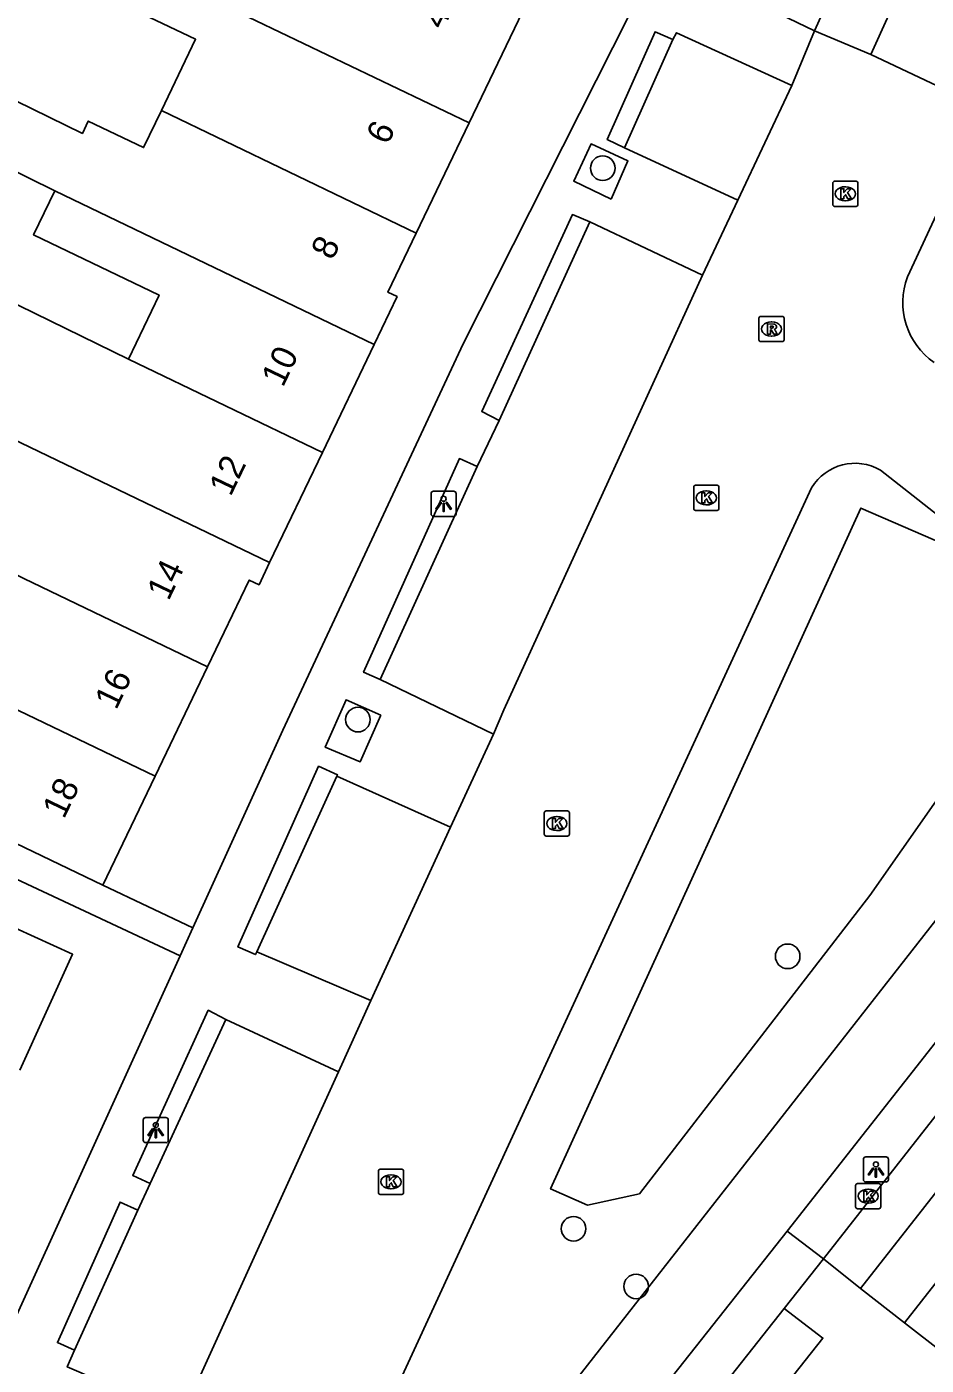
# Model space of a CAD drawing. Extents: x 161355 to 162026, y 386504 to 387459.
# Drawn here: x 161710.6 to 161746.4, y 387097.6 to 387150.7 of the extents above; entities that cross this region are included whole.
import ezdxf

# ---------------------------------------------------------------- set-up
doc = ezdxf.new("R2010")
doc.units = 0
for name, color, linetype in [('IMGEO_Boom', 7, 'Continuous'), ('IMGEO_Groenvoorziening', 7, 'Continuous'), ('IMGEO_Kolk', 7, 'Continuous'), ('IMGEO_Lichtpunt', 7, 'Continuous'), ('IMGEO_Pand', 7, 'Continuous'), ('IMGEO_Pand_nummerreeks', 7, 'Continuous'), ('IMGEO_Parkeervlak_open', 7, 'Continuous'), ('IMGEO_Rijbaan_lokaal_gesloten', 7, 'Continuous'), ('IMGEO_Rijbaan_lokaal_open', 7, 'Continuous'), ('IMGEO_Rioolput', 7, 'Continuous'), ('IMGEO_Voetpad_open', 7, 'Continuous')]:
    doc.layers.add(name, color=color, linetype=linetype)

msp = doc.modelspace()

# ---------------------------------------------------------------- linework, layer by layer
at = {"layer": 'IMGEO_Boom'}
for centre in [(161733.509, 387145.125), (161723.775, 387123.211), (161740.861, 387113.805), (161732.348, 387102.979), (161734.836, 387100.687)]:
    msp.add_circle(centre, 0.489, dxfattribs=at)
at = {"layer": 'IMGEO_Groenvoorziening'}
for points in [[(161732.906, 387103.919), (161734.966, 387104.367), (161744.13, 387116.217), (161750.489, 387125.292), (161750.19, 387127.083), (161747.533, 387129.979), (161743.772, 387131.62), (161731.438, 387104.561), (161732.906, 387103.919)], [(161754.575, 387125.244), (161721.108, 387082.503), (161720.967, 387082.324), (161720.779, 387082.098), (161720.566, 387081.91), (161720.265, 387081.76), (161719.863, 387081.722), (161719.475, 387081.835), (161719.261, 387082.023), (161719.123, 387082.287), (161718.998, 387082.525), (161718.9, 387082.743)]]:
    msp.add_lwpolyline(points, dxfattribs=at)
at = {"layer": 'IMGEO_Kolk'}
for p, q in [((161742.653, 387143.68), (161742.653, 387144.532)), ((161742.728, 387144.606), (161743.58, 387144.606)), ((161743.141, 387144.386), (161743.166, 387144.386)), ((161743.654, 387144.532), (161743.654, 387143.68)), ((161743.58, 387143.606), (161742.728, 387143.606)), ((161743.164, 387143.826), (161743.139, 387143.826)), ((161737.125, 387131.597), (161737.125, 387132.449)), ((161737.2, 387132.523), (161738.052, 387132.523)), ((161738.126, 387132.449), (161738.126, 387131.597)), ((161737.613, 387132.303), (161737.638, 387132.303)), ((161738.052, 387131.523), (161737.2, 387131.523)), ((161737.636, 387131.743), (161737.611, 387131.743)), ((161731.185, 387118.656), (161731.185, 387119.508)), ((161731.26, 387119.582), (161732.112, 387119.582)), ((161731.673, 387119.362), (161731.698, 387119.362)), ((161732.186, 387119.508), (161732.186, 387118.656)), ((161732.112, 387118.582), (161731.26, 387118.582)), ((161731.696, 387118.802), (161731.671, 387118.802)), ((161724.591, 387104.419), (161724.591, 387105.271)), ((161724.666, 387105.345), (161725.518, 387105.345)), ((161725.592, 387105.271), (161725.592, 387104.419)), ((161725.079, 387105.125), (161725.104, 387105.125)), ((161743.636, 387104.774), (161744.488, 387104.774)), ((161725.518, 387104.345), (161724.666, 387104.345)), ((161725.102, 387104.565), (161725.077, 387104.565)), ((161743.561, 387103.848), (161743.561, 387104.7)), ((161744.049, 387104.554), (161744.074, 387104.554)), ((161744.562, 387104.7), (161744.562, 387103.848)), ((161744.488, 387103.774), (161743.636, 387103.774)), ((161744.072, 387103.994), (161744.047, 387103.994))]:
    msp.add_line(p, q, dxfattribs=at)
for points in [[(161742.653, 387143.68), (161742.653, 387144.532)], [(161742.728, 387144.606), (161743.58, 387144.606)], [(161742.974, 387144.306), (161743.097, 387144.306), (161743.097, 387144.155), (161743.227, 387144.306), (161743.391, 387144.306), (161743.245, 387144.155), (161743.398, 387143.906), (161743.246, 387143.906), (161743.161, 387144.07), (161743.097, 387144.003), (161743.097, 387143.906), (161742.974, 387143.906), (161742.974, 387144.306)], [(161743.654, 387144.532), (161743.654, 387143.68)], [(161743.58, 387143.606), (161742.728, 387143.606)], [(161737.125, 387131.597), (161737.125, 387132.449)], [(161737.2, 387132.523), (161738.052, 387132.523)], [(161738.126, 387132.449), (161738.126, 387131.597)], [(161737.446, 387132.223), (161737.569, 387132.223), (161737.569, 387132.072), (161737.699, 387132.223), (161737.863, 387132.223), (161737.717, 387132.072), (161737.87, 387131.823), (161737.718, 387131.823), (161737.633, 387131.987), (161737.569, 387131.92), (161737.569, 387131.823), (161737.446, 387131.823), (161737.446, 387132.223)], [(161738.052, 387131.523), (161737.2, 387131.523)], [(161731.185, 387118.656), (161731.185, 387119.508)], [(161731.26, 387119.582), (161732.112, 387119.582)], [(161731.506, 387119.282), (161731.629, 387119.282), (161731.629, 387119.131), (161731.759, 387119.282), (161731.923, 387119.282), (161731.777, 387119.131), (161731.93, 387118.882), (161731.778, 387118.882), (161731.693, 387119.046), (161731.629, 387118.979), (161731.629, 387118.882), (161731.506, 387118.882), (161731.506, 387119.282)], [(161732.186, 387119.508), (161732.186, 387118.656)], [(161732.112, 387118.582), (161731.26, 387118.582)], [(161724.591, 387104.419), (161724.591, 387105.271)], [(161724.666, 387105.345), (161725.518, 387105.345)], [(161725.592, 387105.271), (161725.592, 387104.419)], [(161724.912, 387105.045), (161725.035, 387105.045), (161725.035, 387104.894), (161725.165, 387105.045), (161725.329, 387105.045), (161725.183, 387104.894), (161725.336, 387104.645), (161725.184, 387104.645), (161725.099, 387104.809), (161725.035, 387104.742), (161725.035, 387104.645), (161724.912, 387104.645), (161724.912, 387105.045)], [(161743.636, 387104.774), (161744.488, 387104.774)], [(161725.518, 387104.345), (161724.666, 387104.345)], [(161743.561, 387103.848), (161743.561, 387104.7)], [(161743.882, 387104.474), (161744.005, 387104.474), (161744.005, 387104.323), (161744.135, 387104.474), (161744.299, 387104.474), (161744.153, 387104.323), (161744.306, 387104.074), (161744.154, 387104.074), (161744.069, 387104.238), (161744.005, 387104.171), (161744.005, 387104.074), (161743.882, 387104.074), (161743.882, 387104.474)], [(161744.562, 387104.7), (161744.562, 387103.848)], [(161744.488, 387103.774), (161743.636, 387103.774)]]:
    msp.add_lwpolyline(points, dxfattribs=at)
for centre, start, end in [((161742.73, 387144.53), 91.552, 178.448), ((161742.73, 387144.53), 91.552, 178.448), ((161743.578, 387144.53), 1.552, 88.448), ((161743.578, 387144.53), 1.552, 88.448), ((161742.73, 387143.682), 181.552, 268.448), ((161742.73, 387143.682), 181.552, 268.448), ((161743.578, 387143.682), 271.552, 358.448), ((161743.578, 387143.682), 271.552, 358.448), ((161737.202, 387132.447), 91.552, 178.448), ((161737.202, 387132.447), 91.552, 178.448), ((161738.05, 387132.447), 1.552, 88.448), ((161738.05, 387132.447), 1.552, 88.448), ((161737.202, 387131.599), 181.552, 268.448), ((161737.202, 387131.599), 181.552, 268.448), ((161738.05, 387131.599), 271.552, 358.448), ((161738.05, 387131.599), 271.552, 358.448), ((161731.262, 387119.506), 91.552, 178.448), ((161731.262, 387119.506), 91.552, 178.448), ((161732.11, 387119.506), 1.552, 88.448), ((161732.11, 387119.506), 1.552, 88.448), ((161731.262, 387118.658), 181.552, 268.448), ((161731.262, 387118.658), 181.552, 268.448), ((161732.11, 387118.658), 271.552, 358.448), ((161732.11, 387118.658), 271.552, 358.448), ((161724.668, 387105.269), 91.552, 178.448), ((161724.668, 387105.269), 91.552, 178.448), ((161725.516, 387105.269), 1.552, 88.448), ((161725.516, 387105.269), 1.552, 88.448), ((161743.638, 387104.698), 91.552, 178.448), ((161743.638, 387104.698), 91.552, 178.448), ((161744.486, 387104.698), 1.552, 88.448), ((161744.486, 387104.698), 1.552, 88.448), ((161724.668, 387104.421), 181.552, 268.448), ((161724.668, 387104.421), 181.552, 268.448), ((161725.516, 387104.421), 271.552, 358.448), ((161725.516, 387104.421), 271.552, 358.448), ((161743.638, 387103.85), 181.552, 268.448), ((161743.638, 387103.85), 181.552, 268.448), ((161744.486, 387103.85), 271.552, 358.448), ((161744.486, 387103.85), 271.552, 358.448)]:
    msp.add_arc(centre, 0.0765, start, end, dxfattribs=at)
for centre, major_axis, ratio, start_param, end_param in [((161743.14, 387144.106), (-0.387, 0.002), 0.722429, 4.712389, 7.853982), ((161743.165, 387144.106), (-0.39, 0.002), 0.717154, 1.570796, 4.712389), ((161737.612, 387132.023), (-0.387, 0.002), 0.722429, 4.712389, 7.853982), ((161737.637, 387132.023), (-0.39, 0.002), 0.717154, 1.570796, 4.712389), ((161731.672, 387119.082), (-0.387, 0.002), 0.722429, 4.712389, 7.853982), ((161731.697, 387119.082), (-0.39, 0.002), 0.717154, 1.570796, 4.712389), ((161725.078, 387104.845), (-0.387, 0.002), 0.722429, 4.712389, 7.853982), ((161725.103, 387104.845), (-0.39, 0.002), 0.717154, 1.570796, 4.712389), ((161744.048, 387104.274), (-0.387, 0.002), 0.722429, 4.712389, 7.853982), ((161744.073, 387104.274), (-0.39, 0.002), 0.717154, 1.570796, 4.712389)]:
    msp.add_ellipse(centre, major_axis=major_axis, ratio=ratio, start_param=start_param, end_param=end_param, dxfattribs=at)
at = {"layer": 'IMGEO_Lichtpunt'}
for p, q in [((161726.683, 387132.19), (161726.683, 387131.383)), ((161726.683, 387132.19), (161726.683, 387131.383)), ((161727.585, 387132.285), (161726.777, 387132.285)), ((161727.585, 387132.285), (161726.777, 387132.285)), ((161727.679, 387131.383), (161727.679, 387132.19)), ((161727.679, 387131.383), (161727.679, 387132.19)), ((161726.777, 387131.289), (161727.585, 387131.289)), ((161726.777, 387131.289), (161727.585, 387131.289)), ((161716.144, 387107.397), (161715.336, 387107.397)), ((161716.144, 387107.397), (161715.336, 387107.397)), ((161715.242, 387107.302), (161715.242, 387106.495)), ((161715.242, 387107.302), (161715.242, 387106.495)), ((161716.238, 387106.495), (161716.238, 387107.302)), ((161716.238, 387106.495), (161716.238, 387107.302)), ((161715.336, 387106.401), (161716.144, 387106.401)), ((161715.336, 387106.401), (161716.144, 387106.401)), ((161744.771, 387105.834), (161743.963, 387105.834)), ((161744.771, 387105.834), (161743.963, 387105.834)), ((161743.869, 387105.739), (161743.869, 387104.932)), ((161743.869, 387105.739), (161743.869, 387104.932)), ((161744.865, 387104.932), (161744.865, 387105.739)), ((161744.865, 387104.932), (161744.865, 387105.739)), ((161743.963, 387104.838), (161744.771, 387104.838)), ((161743.963, 387104.838), (161744.771, 387104.838))]:
    msp.add_line(p, q, dxfattribs=at)
for points in [[(161727.057, 387131.854), (161727.096, 387131.826), (161726.908, 387131.564), (161726.87, 387131.591), (161727.057, 387131.854)], [(161727.159, 387131.806), (161727.206, 387131.806), (161727.206, 387131.484), (161727.159, 387131.484), (161727.159, 387131.806)], [(161727.269, 387131.826), (161727.307, 387131.853), (161727.494, 387131.591), (161727.455, 387131.563), (161727.269, 387131.826)], [(161715.616, 387106.966), (161715.655, 387106.938), (161715.467, 387106.676), (161715.429, 387106.703), (161715.616, 387106.966)], [(161715.718, 387106.918), (161715.765, 387106.918), (161715.765, 387106.596), (161715.718, 387106.596), (161715.718, 387106.918)], [(161715.828, 387106.938), (161715.866, 387106.965), (161716.053, 387106.703), (161716.014, 387106.675), (161715.828, 387106.938)], [(161744.243, 387105.403), (161744.282, 387105.375), (161744.094, 387105.113), (161744.056, 387105.14), (161744.243, 387105.403)], [(161744.345, 387105.355), (161744.392, 387105.355), (161744.392, 387105.033), (161744.345, 387105.033), (161744.345, 387105.355)], [(161744.455, 387105.375), (161744.493, 387105.402), (161744.68, 387105.14), (161744.641, 387105.112), (161744.455, 387105.375)]]:
    msp.add_lwpolyline(points, dxfattribs=at)
for centre in [(161727.182, 387131.988), (161715.741, 387107.1), (161744.368, 387105.537)]:
    msp.add_circle(centre, 0.0994, dxfattribs=at)
for centre, start, end in [((161726.777, 387132.19), 90, 180), ((161726.777, 387132.19), 90, 180), ((161727.585, 387132.19), 0, 90), ((161727.585, 387132.19), 0, 90), ((161726.777, 387131.383), 180, 270), ((161726.777, 387131.383), 180, 270), ((161727.585, 387131.383), 270, 0), ((161727.585, 387131.383), 270, 360), ((161715.336, 387107.302), 90, 180), ((161715.336, 387107.302), 90, 180), ((161716.144, 387107.302), 0, 90), ((161716.144, 387107.302), 0, 90), ((161715.336, 387106.495), 180, 270), ((161715.336, 387106.495), 180, 270), ((161716.144, 387106.495), 270, 0), ((161716.144, 387106.495), 270, 360), ((161743.963, 387105.739), 90, 180), ((161743.963, 387105.739), 90, 180), ((161744.771, 387105.739), 0, 90), ((161744.771, 387105.739), 0, 90), ((161743.963, 387104.932), 180, 270), ((161743.963, 387104.932), 180, 270), ((161744.771, 387104.932), 270, 0), ((161744.771, 387104.932), 270, 360)]:
    msp.add_arc(centre, 0.0946, start, end, dxfattribs=at)
at = {"layer": 'IMGEO_Pand'}
for points in [[(161724.018, 387156.941), (161723.347, 387155.542), (161730.65, 387152.038), (161728.195, 387146.921)], [(161715.967, 387147.422), (161717.322, 387150.246), (161715.232, 387151.248), (161715.973, 387152.793)], [(161715.973, 387152.793), (161728.195, 387146.921)], [(161715.967, 387147.422), (161715.256, 387145.941), (161713.057, 387146.996), (161712.822, 387146.505), (161706.844, 387149.435), (161705.734, 387147.171), (161706.457, 387146.815), (161711.727, 387144.223)], [(161726.093, 387142.54), (161715.967, 387147.422)], [(161728.195, 387146.921), (161726.093, 387142.54)], [(161711.727, 387144.223), (161710.886, 387142.471), (161715.873, 387140.079), (161714.65, 387137.529)], [(161711.727, 387144.223), (161724.425, 387138.122)], [(161726.093, 387142.54), (161724.968, 387140.195), (161725.335, 387140.019), (161724.425, 387138.122)], [(161714.65, 387137.529), (161709.672, 387139.967), (161708.808, 387138.167), (161707.557, 387135.559)], [(161724.425, 387138.122), (161722.363, 387133.823)], [(161722.363, 387133.823), (161714.65, 387137.529)], [(161720.266, 387129.452), (161707.557, 387135.559)], [(161722.363, 387133.823), (161720.266, 387129.452)], [(161708.329, 387129.872), (161710.49, 387128.825), (161717.802, 387125.311)], [(161720.266, 387129.452), (161719.844, 387128.573), (161719.456, 387128.759), (161717.802, 387125.311)], [(161703.483, 387126.836), (161715.715, 387120.96)], [(161717.802, 387125.311), (161715.715, 387120.96)], [(161713.64, 387116.635), (161709.132, 387118.797), (161706.374, 387120.12), (161701.405, 387122.504)], [(161715.715, 387120.96), (161713.64, 387116.635)], [(161697.903, 387114.931), (161696.422, 387115.597), (161697.432, 387117.821), (161698.912, 387117.154), (161699.995, 387119.536), (161704.983, 387117.27), (161707.879, 387115.954), (161712.431, 387113.886), (161710.337, 387109.279)]]:
    msp.add_lwpolyline(points, dxfattribs=at)
at = {"layer": 'IMGEO_Parkeervlak_open'}
for points in [[(161736.296, 387150.242), (161734.374, 387145.938)], [(161729.391, 387135.096), (161732.991, 387142.991)], [(161724.663, 387124.806), (161728.522, 387133.267)], [(161722.939, 387120.962), (161719.757, 387113.98)], [(161718.523, 387111.292), (161715.514, 387104.772)], [(161715.022, 387103.715), (161712.507, 387098.158)]]:
    msp.add_lwpolyline(points, dxfattribs=at)
at = {"layer": 'IMGEO_Rijbaan_lokaal_gesloten'}
for points in [[(161742.29, 387101.785), (161765.777, 387131.733), (161770.203, 387137.573)], [(161771.79, 387136.62), (161767.153, 387130.425), (161743.755, 387100.6)], [(161745.507, 387099.246), (161767.667, 387127.477), (161773.404, 387135.036)], [(161743.755, 387100.6), (161742.29, 387101.785)], [(161746.988, 387098.093), (161745.507, 387099.246)]]:
    msp.add_lwpolyline(points, dxfattribs=at)
at = {"layer": 'IMGEO_Rijbaan_lokaal_open'}
for points in [[(161741.028, 387148.403), (161741.924, 387150.577)], [(161741.924, 387150.577), (161744.169, 387149.635)], [(161744.169, 387149.635), (161748.484, 387147.603)], [(161738.877, 387143.847), (161741.028, 387148.403)], [(161748.619, 387147.247), (161745.626, 387140.8)], [(161737.478, 387140.871), (161738.877, 387143.847)], [(161729.166, 387122.629), (161729.577, 387123.603), (161737.478, 387140.871)], [(161754.575, 387125.244), (161744.547, 387133.122)], [(161741.812, 387132.423), (161718.9, 387082.743)], [(161727.458, 387118.934), (161729.166, 387122.629)], [(161724.287, 387112.046), (161727.458, 387118.934)], [(161723.004, 387109.212), (161724.287, 387112.046)], [(161716.771, 387095.536), (161723.004, 387109.212)], [(161740.72, 387099.817), (161742.29, 387101.785)], [(161745.507, 387099.246), (161743.755, 387100.6)], [(161690.719, 387036.239), (161693.118, 387039.45), (161698.781, 387046.763), (161740.72, 387099.817)], [(161690.719, 387036.239), (161692.257, 387035.086), (161694.354, 387037.936), (161700.184, 387045.485), (161742.263, 387098.632), (161740.72, 387099.817)]]:
    msp.add_lwpolyline(points, dxfattribs=at)
for centre, radius, start, end in [((161748.324, 387139.777), 2.885, 159.2349, 235.4155), ((161743.532, 387131.392), 2.005, 59.6006, 149.0725)]:
    msp.add_arc(centre, radius, start, end, dxfattribs=at)
at = {"layer": 'IMGEO_Rioolput'}
for p, q in [((161739.718, 387138.307), (161739.718, 387139.159)), ((161739.793, 387139.233), (161740.645, 387139.233)), ((161740.206, 387139.013), (161740.231, 387139.013)), ((161740.719, 387139.159), (161740.719, 387138.307)), ((161740.229, 387138.453), (161740.204, 387138.453)), ((161740.645, 387138.233), (161739.793, 387138.233))]:
    msp.add_line(p, q, dxfattribs=at)
for points in [[(161739.718, 387138.307), (161739.718, 387139.159)], [(161739.793, 387139.233), (161740.645, 387139.233)], [(161740.307, 387138.931), (161740.055, 387138.933), (161740.055, 387138.533)], [(161740.233, 387138.852), (161740.179, 387138.852), (161740.179, 387138.771)], [(161740.719, 387139.159), (161740.719, 387138.307)], [(161740.055, 387138.533), (161740.179, 387138.533), (161740.179, 387138.695), (161740.19, 387138.695)], [(161740.179, 387138.771), (161740.231, 387138.771)], [(161740.237, 387138.666), (161740.308, 387138.533), (161740.448, 387138.533), (161740.383, 387138.659)], [(161740.645, 387138.233), (161739.793, 387138.233)]]:
    msp.add_lwpolyline(points, dxfattribs=at)
for centre, radius, start, end in [((161739.795, 387139.157), 0.0765, 91.552, 178.448), ((161739.795, 387139.157), 0.0765, 91.552, 178.448), ((161740.215, 387138.96), 0.19, 274.7715, 282.9687), ((161740.239, 387138.756), 0.0964, 77.0061, 93.1865), ((161740.253, 387138.813), 0.0378, 276.6634, 79.6772), ((161740.306, 387138.821), 0.109, 350.3612, 89.416), ((161740.304, 387138.821), 0.112, 277.5842, 350.9817), ((161740.643, 387139.157), 0.0765, 1.552, 88.448), ((161740.643, 387139.157), 0.0765, 1.552, 88.448), ((161739.795, 387138.309), 0.0765, 181.552, 268.448), ((161739.795, 387138.309), 0.0765, 181.552, 268.448), ((161740.189, 387138.642), 0.0533, 26.0293, 88.6989), ((161740.288, 387138.606), 0.108, 29.5134, 73.7905), ((161740.643, 387138.309), 0.0765, 271.552, 358.448), ((161740.643, 387138.309), 0.0765, 271.552, 358.448)]:
    msp.add_arc(centre, radius, start, end, dxfattribs=at)
for centre, major_axis, ratio, start_param, end_param in [((161740.205, 387138.733), (-0.387, 0.002), 0.722429, 4.712389, 7.853982), ((161740.23, 387138.733), (-0.39, 0.002), 0.717154, 1.570796, 4.712389)]:
    msp.add_ellipse(centre, major_axis=major_axis, ratio=ratio, start_param=start_param, end_param=end_param, dxfattribs=at)
at = {"layer": 'IMGEO_Voetpad_open'}
for points in [[(161741.924, 387150.577), (161745.758, 387159.045), (161746.552, 387160.73), (161750.844, 387170.123)], [(161753.155, 387169.437), (161744.169, 387149.635)], [(161741.924, 387150.577), (161735.746, 387153.559)], [(161734.577, 387151.232), (161727.954, 387138.147), (161720.797, 387122.792), (161717.219, 387114.936)], [(161734.374, 387145.938), (161733.69, 387146.262), (161735.592, 387150.542), (161736.296, 387150.242)], [(161736.296, 387150.242), (161736.44, 387150.507), (161741.028, 387148.403)], [(161733.85, 387143.889), (161732.359, 387144.613), (161733.047, 387146.087), (161734.511, 387145.415), (161733.85, 387143.889)], [(161738.877, 387143.847), (161734.374, 387145.938)], [(161729.391, 387135.096), (161728.696, 387135.449), (161732.304, 387143.283), (161732.991, 387142.991)], [(161732.991, 387142.991), (161737.478, 387140.871)], [(161728.522, 387133.267), (161729.391, 387135.096)], [(161724.663, 387124.806), (161723.999, 387125.092), (161727.814, 387133.583), (161728.522, 387133.267)], [(161680.849, 387130.31), (161682.113, 387129.711), (161682.215, 387129.967), (161716.712, 387113.822)], [(161729.166, 387122.629), (161724.663, 387124.806)], [(161724.692, 387123.382), (161723.304, 387124.001), (161722.478, 387122.115), (161723.861, 387121.529), (161724.692, 387123.382)], [(161719.757, 387113.98), (161719.701, 387113.873), (161719.005, 387114.177), (161722.211, 387121.358), (161722.97, 387121.017), (161722.939, 387120.962)], [(161722.939, 387120.962), (161727.458, 387118.934)], [(161755.019, 387120.91), (161740.841, 387102.878)], [(161713.64, 387116.635), (161717.219, 387114.936)], [(161717.219, 387114.936), (161716.712, 387113.822)], [(161716.712, 387113.822), (161685.869, 387046.107), (161681.882, 387036.937), (161680.176, 387036.531), (161678.254, 387037.458)], [(161724.287, 387112.046), (161719.757, 387113.98)], [(161715.514, 387104.772), (161714.825, 387105.095), (161717.829, 387111.663), (161718.523, 387111.292)], [(161718.523, 387111.292), (161723.004, 387109.212)], [(161715.022, 387103.715), (161715.514, 387104.772)], [(161712.507, 387098.158), (161711.827, 387098.454), (161714.323, 387104.038), (161715.022, 387103.715)], [(161740.841, 387102.878), (161713.744, 387068.636)], [(161742.29, 387101.785), (161740.841, 387102.878)], [(161716.771, 387095.536), (161712.222, 387097.488), (161712.507, 387098.158)]]:
    msp.add_lwpolyline(points, dxfattribs=at)

# ---------------------------------------------------------------- texts
at = {"layer": 'IMGEO_Pand_nummerreeks'}
for s, rotation, p in [('4', 64.3694, (161727.16, 387150.59)), ('6', 64.3694, (161724.962, 387146.011)), ('8', 64.3718, (161722.768, 387141.433)), ('10', 64.3715, (161720.795, 387136.384)), ('12', 64.3715, (161718.714, 387132.044)), ('14', 64.3718, (161716.248, 387127.899)), ('16', 64.3725, (161714.168, 387123.564)), ('18', 64.3725, (161712.09, 387119.232))]:
    msp.add_text(s, height=1, rotation=rotation, dxfattribs=at).set_placement(p)

doc.saveas('drawing.dxf')
